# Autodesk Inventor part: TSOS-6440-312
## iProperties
Author: Ron Crain
Shininess: 25.0
Angle Display Precision: 2
Document Length Units: 11272
Document Angle Units: 11286
Document Time Units: 11279
Document Mass Units: 11290
Document Length Units Precision: 3
Document Angle Units Precision: 2
Compacted: True
PropertySet Name: _Private Model Information
Created: 2001-09
Part Number: TSOS-6440-312
Material: Stainless Steel, Austenitic
Description: STANDOFF, THK WALL THREADED , SELF CLINCH, 4-40 UNC X .312
Vendor: PENN ENG. & MFG
Document SubType Name: Modeling
Designer: Ron Crain
Control State: 0
Master: False
Checked Out: False
PropertySet Name: Design Tracking Control
Density: 7.84
Volumn: 0.17245559573138858
Area: 3.4800931280430336
PropertySet Name: Model Information
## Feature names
1. Extrusion1
2. Extrusion2
3. Revolution1
4. Revolution2
5. Rectangular Pattern1
6. Hole1
7. Chamfer5
8. Chamfer3
